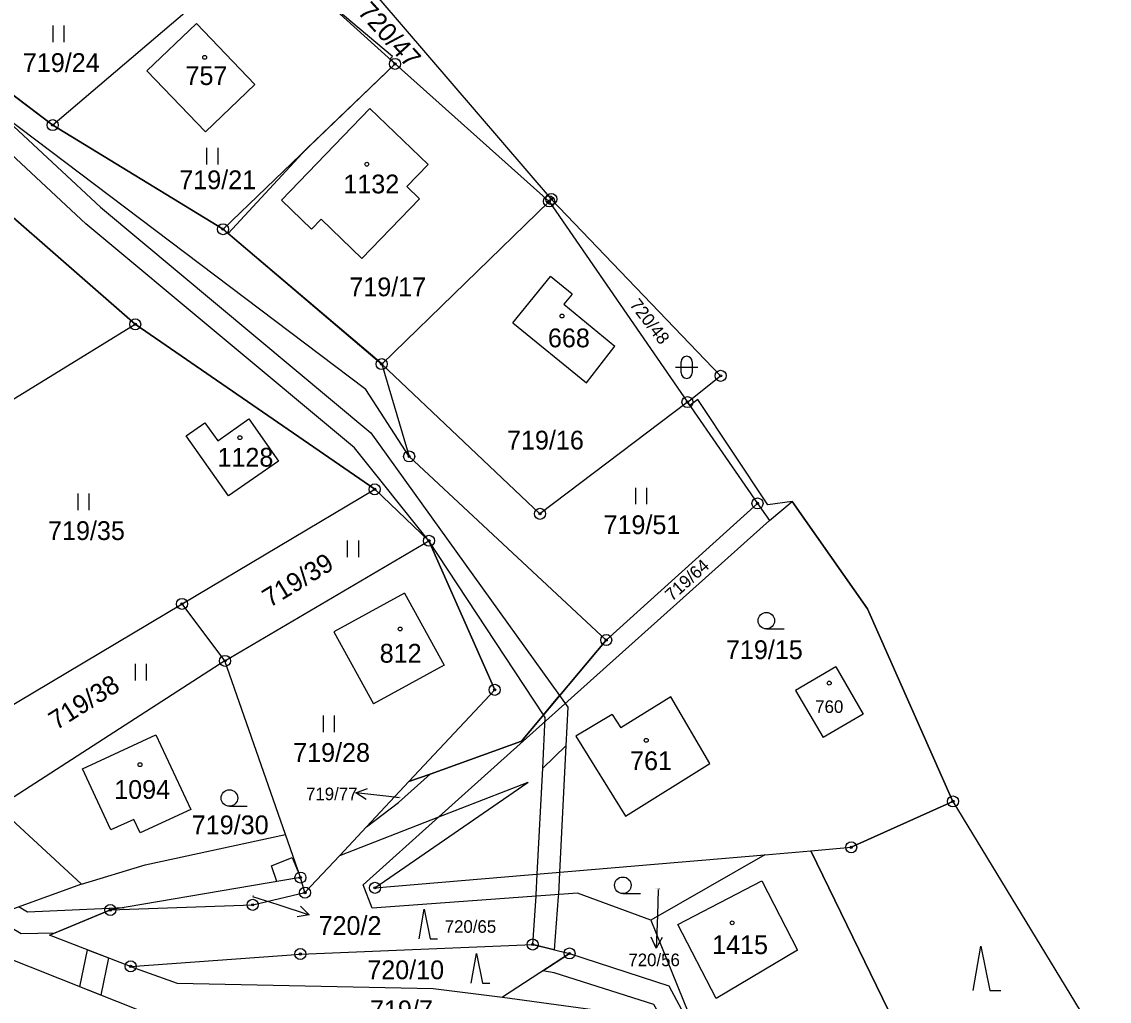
# Model space of a CAD drawing. Extents: x -439246 to -433691, y -1130252 to -1121148.
# Drawn here: x -436567.4 to -436469, y -1125891.5 to -1125802.9 of the extents above; entities that cross this region are included whole.
import ezdxf

# ---------------------------------------------------------------- set-up
doc = ezdxf.new("R2010")
doc.units = 0
for name, color, linetype in [('Vrstva 1', 7, 'Continuous'), ('Vrstva 16', 7, 'Continuous'), ('Vrstva 18', 7, 'Continuous'), ('Vrstva 19', 7, 'Continuous'), ('Vrstva 24', 7, 'Continuous'), ('Vrstva 25', 7, 'Continuous'), ('Vrstva 3', 7, 'Continuous'), ('Vrstva 30', 7, 'Continuous'), ('Vrstva 37', 7, 'Continuous'), ('Vrstva 52', 7, 'Continuous'), ('Vrstva 6', 7, 'Continuous')]:
    doc.layers.add(name, color=color, linetype=linetype)

msp = doc.modelspace()

# ---------------------------------------------------------------- linework, layer by layer
at = {"layer": 'Vrstva 1'}
for p, q in [((-436545.44, -1125795.95), (-436564.59, -1125812.25)), ((-436564.59, -1125812.25), (-436578.24, -1125801.93)), ((-436533.61, -1125806.71), (-436549.17, -1125821.67)), ((-436549.17, -1125821.67), (-436564.59, -1125812.25)), ((-436534.82, -1125833.88), (-436519.67, -1125819.15)), ((-436549.17, -1125821.67), (-436534.82, -1125833.88)), ((-436534.82, -1125833.88), (-436532.33, -1125842.24)), ((-436520.5, -1125847.43), (-436534.82, -1125833.88)), ((-436532.33, -1125842.24), (-436536.26, -1125836.19)), ((-436507.15, -1125837.32), (-436520.5, -1125847.43)), ((-436507.15, -1125837.32), (-436500.81, -1125846.49)), ((-436514.5, -1125858.85), (-436532.33, -1125842.24))]:
    msp.add_line(p, q, dxfattribs=at)
for points in [[(-436541.87, -1125792.85), (-436519.47, -1125818.94)], [(-436536.26, -1125836.19), (-436590.69, -1125795.04)], [(-436545.44, -1125795.95), (-436533.61, -1125806.71)], [(-436594.14, -1125797.88), (-436557.12, -1125830.28)], [(-436551.59, -1125803.04), (-436556.06, -1125807.34)], [(-436551.59, -1125803.04), (-436546.29, -1125808.56)], [(-436519.67, -1125819.15), (-436533.61, -1125806.71)], [(-436556.06, -1125807.34), (-436550.76, -1125812.86)], [(-436546.29, -1125808.56), (-436550.76, -1125812.86)], [(-436543.89, -1125819.04), (-436535.88, -1125810.74)], [(-436535.88, -1125810.74), (-436530.62, -1125815.81)], [(-436530.62, -1125815.81), (-436532.55, -1125817.8)], [(-436532.55, -1125817.8), (-436531.39, -1125818.92)], [(-436541.17, -1125821.67), (-436543.89, -1125819.04)], [(-436531.39, -1125818.92), (-436536.6, -1125824.32)], [(-436519.47, -1125818.94), (-436519.67, -1125819.15)], [(-436507.15, -1125837.32), (-436504.15, -1125834.94), (-436519.47, -1125818.94)], [(-436519.67, -1125819.15), (-436507.15, -1125837.32)], [(-436540.29, -1125820.76), (-436541.17, -1125821.67)], [(-436536.6, -1125824.32), (-436540.29, -1125820.76)], [(-436522.95, -1125830.14), (-436519.53, -1125825.96)], [(-436517.59, -1125827.54), (-436519.53, -1125825.96)], [(-436517.59, -1125827.54), (-436518.35, -1125828.47)], [(-436518.35, -1125828.47), (-436513.71, -1125832.27)], [(-436581.96, -1125845.52), (-436557.12, -1125830.28)], [(-436557.12, -1125830.28), (-436535.45, -1125845.21)], [(-436522.95, -1125830.14), (-436516.29, -1125835.59)], [(-436516.29, -1125835.59), (-436513.71, -1125832.27)], [(-436552.5, -1125840.37), (-436550.81, -1125839.19)], [(-436550.81, -1125839.19), (-436549.66, -1125840.83)], [(-436549.66, -1125840.83), (-436546.83, -1125838.84)], [(-436546.83, -1125838.84), (-436544.15, -1125842.66)], [(-436548.69, -1125845.81), (-436552.5, -1125840.37)], [(-436544.15, -1125842.66), (-436548.69, -1125845.81)], [(-436552.88, -1125855.58), (-436535.45, -1125845.21)], [(-436535.45, -1125845.21), (-436530.54, -1125849.87)], [(-436500.81, -1125846.49), (-436514.5, -1125858.85)], [(-436500.81, -1125846.49), (-436499.73, -1125848.04)], [(-436499.73, -1125848.04), (-436497.68, -1125846.33), (-436490.86, -1125856.02), (-436483.12, -1125873.46)], [(-436529.66, -1125874.86), (-436523.17, -1125869.03), (-436499.73, -1125848.04)], [(-436549, -1125860.74), (-436530.54, -1125849.87)], [(-436530.54, -1125849.87), (-436524.59, -1125863.36)], [(-436532.74, -1125854.6), (-436539.14, -1125858.11)], [(-436532.74, -1125854.6), (-436529.16, -1125861.12)], [(-436570.83, -1125866.25), (-436552.88, -1125855.58)], [(-436549, -1125860.74), (-436552.88, -1125855.58)], [(-436539.14, -1125858.11), (-436535.56, -1125864.63)], [(-436522.18, -1125868.01), (-436514.5, -1125858.85)], [(-436549, -1125860.74), (-436569.55, -1125873.98)], [(-436543.53, -1125876.45), (-436549, -1125860.74)], [(-436529.16, -1125861.12), (-436535.56, -1125864.63)], [(-436493.73, -1125861.29), (-436497.36, -1125863.41)], [(-436493.73, -1125861.29), (-436491.25, -1125865.57)], [(-436524.59, -1125863.36), (-436532.36, -1125871.67)], [(-436508.64, -1125863.99), (-436513.18, -1125866.81)], [(-436505.11, -1125870.04), (-436508.64, -1125863.99)], [(-436497.36, -1125863.41), (-436494.88, -1125867.68)], [(-436513.95, -1125865.58), (-436517.24, -1125867.56)], [(-436513.95, -1125865.58), (-436513.18, -1125866.81)], [(-436491.25, -1125865.57), (-436494.88, -1125867.68)], [(-436561.88, -1125870.5), (-436555.27, -1125867.43)], [(-436555.27, -1125867.43), (-436552.1, -1125874.2)], [(-436530.44, -1125870.98), (-436522.18, -1125868.01)], [(-436517.24, -1125867.56), (-436512.76, -1125874.78)], [(-436512.76, -1125874.78), (-436505.11, -1125870.04)], [(-436559.33, -1125876.03), (-436561.88, -1125870.5)], [(-436536.2, -1125875.77), (-436533.3, -1125873.55), (-436530.44, -1125870.98)], [(-436532.36, -1125871.67), (-436530.44, -1125870.98)], [(-436532.36, -1125871.67), (-436536.2, -1125875.77)], [(-436535.43, -1125881.28), (-436521.57, -1125871.71)], [(-436529.66, -1125874.86), (-436521.57, -1125871.71)], [(-436569.55, -1125873.98), (-436561.98, -1125880.95)], [(-436552.1, -1125874.2), (-436556.66, -1125876.31)], [(-436483.12, -1125873.46), (-436492.33, -1125877.61)], [(-436557.26, -1125875.09), (-436559.33, -1125876.03)], [(-436556.66, -1125876.31), (-436557.26, -1125875.09)], [(-436538.6, -1125878.34), (-436529.66, -1125874.86)], [(-436536.5, -1125881), (-436529.66, -1125874.86)], [(-436536.2, -1125875.77), (-436538.6, -1125878.34)], [(-436556.21, -1125879.19), (-436543.53, -1125876.45)], [(-436542.17, -1125880.35), (-436543.53, -1125876.45)], [(-436500.14, -1125878.28), (-436495.97, -1125877.92)], [(-436495.97, -1125877.92), (-436492.33, -1125877.61)], [(-436495.97, -1125877.92), (-436475.95, -1125919.12), (-436482.11, -1125922.67)], [(-436538.6, -1125878.34), (-436541.76, -1125881.71)], [(-436535.43, -1125881.28), (-436500.14, -1125878.28)], [(-436500.14, -1125878.28), (-436510.45, -1125884.2)], [(-436561.98, -1125880.95), (-436556.21, -1125879.19)], [(-436561.98, -1125880.95), (-436568.15, -1125883.19)], [(-436542.17, -1125880.35), (-436559.37, -1125883.28)], [(-436541.76, -1125881.71), (-436542.17, -1125880.35)], [(-436535.69, -1125883.12), (-436536.5, -1125881)], [(-436508.01, -1125884.59), (-436500.43, -1125880.64), (-436497.2, -1125886.91), (-436504.55, -1125891.31), (-436508.01, -1125884.59)], [(-436546.49, -1125882.82), (-436541.76, -1125881.71)], [(-436517.1, -1125881.75), (-436535.69, -1125883.12)], [(-436510.45, -1125884.2), (-436517.1, -1125881.75)], [(-436559.37, -1125883.28), (-436546.49, -1125882.82)], [(-436564.87, -1125885.56), (-436559.37, -1125883.28)], [(-436510.45, -1125884.2), (-436505.63, -1125896.13)], [(-436557.54, -1125888.39), (-436564.87, -1125885.56)], [(-436571.96, -1125886.32), (-436553.5, -1125893.66)], [(-436542.18, -1125887.27), (-436521.15, -1125886.41)], [(-436521.15, -1125886.41), (-436517.82, -1125887.22)], [(-436557.54, -1125888.39), (-436542.18, -1125887.27)], [(-436517.82, -1125887.22), (-436523.9, -1125891.18)], [(-436557.54, -1125888.39), (-436553.33, -1125889.91)], [(-436553.33, -1125889.91), (-436530.15, -1125890.38)], [(-436530.15, -1125890.38), (-436523.9, -1125891.18)], [(-436523.9, -1125891.18), (-436510.19, -1125893.05)]]:
    msp.add_lwpolyline(points, dxfattribs=at)
at = {"layer": 'Vrstva 16'}
for p, q in [((-436534.17, -1125873.02), (-436537.152, -1125872.69)), ((-436544.22, -1125882.8), (-436541.37, -1125883.736)), ((-436509.87, -1125883.75), (-436509.971, -1125886.748))]:
    msp.add_line(p, q, dxfattribs=at)
for points in [[(-436536.213, -1125873.297), (-436537.152, -1125872.69), (-436536.103, -1125872.303)], [(-436533.24, -1125873.12), (-436534.17, -1125873.02)], [(-436546.5, -1125882.05), (-436544.22, -1125882.8)], [(-436509.8, -1125881.43), (-436509.87, -1125883.75)], [(-436542.164, -1125882.949), (-436541.37, -1125883.736), (-436542.476, -1125883.899)], [(-436509.438, -1125885.766), (-436509.971, -1125886.748), (-436510.437, -1125885.732)]]:
    msp.add_lwpolyline(points, dxfattribs=at)
at = {"layer": 'Vrstva 24'}
for centre, radius in [((-436533.61, -1125806.71), 0.5), ((-436533.61, -1125806.71), 0.1), ((-436564.59, -1125812.25), 0.5), ((-436564.59, -1125812.25), 0.1), ((-436519.67, -1125819.15), 0.5), ((-436519.47, -1125818.94), 0.5), ((-436519.67, -1125819.15), 0.1), ((-436519.47, -1125818.94), 0.1), ((-436549.17, -1125821.67), 0.5), ((-436549.17, -1125821.67), 0.1), ((-436557.12, -1125830.28), 0.5), ((-436557.12, -1125830.28), 0.1), ((-436534.82, -1125833.88), 0.5), ((-436534.82, -1125833.88), 0.1), ((-436504.15, -1125834.94), 0.5), ((-436504.15, -1125834.94), 0.1), ((-436507.15, -1125837.32), 0.5), ((-436507.15, -1125837.32), 0.1), ((-436532.33, -1125842.24), 0.5), ((-436532.33, -1125842.24), 0.1), ((-436535.45, -1125845.21), 0.5), ((-436535.45, -1125845.21), 0.1), ((-436500.81, -1125846.49), 0.5), ((-436500.81, -1125846.49), 0.1), ((-436520.5, -1125847.43), 0.5), ((-436520.5, -1125847.43), 0.1), ((-436530.54, -1125849.87), 0.5), ((-436530.54, -1125849.87), 0.1), ((-436552.88, -1125855.58), 0.5), ((-436552.88, -1125855.58), 0.1), ((-436514.5, -1125858.85), 0.5), ((-436514.5, -1125858.85), 0.1), ((-436549, -1125860.74), 0.5), ((-436549, -1125860.74), 0.1), ((-436524.59, -1125863.36), 0.5), ((-436524.59, -1125863.36), 0.1), ((-436483.12, -1125873.46), 0.5), ((-436483.12, -1125873.46), 0.1), ((-436492.33, -1125877.61), 0.5), ((-436492.33, -1125877.61), 0.1), ((-436542.17, -1125880.35), 0.5), ((-436542.17, -1125880.35), 0.1), ((-436535.43, -1125881.28), 0.5), ((-436541.76, -1125881.71), 0.5), ((-436541.76, -1125881.71), 0.1), ((-436535.43, -1125881.28), 0.1), ((-436559.37, -1125883.28), 0.5), ((-436546.49, -1125882.82), 0.5), ((-436546.49, -1125882.82), 0.1), ((-436559.37, -1125883.28), 0.1), ((-436521.15, -1125886.41), 0.5), ((-436542.18, -1125887.27), 0.5), ((-436521.15, -1125886.41), 0.1), ((-436517.82, -1125887.22), 0.5), ((-436557.54, -1125888.39), 0.5), ((-436542.18, -1125887.27), 0.1), ((-436517.82, -1125887.22), 0.1), ((-436557.54, -1125888.39), 0.1)]:
    msp.add_circle(centre, radius, dxfattribs=at)
at = {"layer": 'Vrstva 25'}
for p, q in [((-436564.54, -1125804.74), (-436564.54, -1125803.24)), ((-436563.54, -1125804.74), (-436563.54, -1125803.24)), ((-436550.63, -1125815.81), (-436550.63, -1125814.31)), ((-436549.63, -1125815.81), (-436549.63, -1125814.31)), ((-436507.72, -1125834.67), (-436507.72, -1125833.67)), ((-436506.72, -1125833.67), (-436506.72, -1125834.67)), ((-436508.22, -1125834.17), (-436506.22, -1125834.17)), ((-436562.28, -1125847.1), (-436562.28, -1125845.6)), ((-436561.28, -1125847.1), (-436561.28, -1125845.6)), ((-436511.83, -1125846.57), (-436511.83, -1125845.07)), ((-436510.83, -1125846.57), (-436510.83, -1125845.07)), ((-436537.9, -1125851.34), (-436537.9, -1125849.84)), ((-436536.9, -1125851.34), (-436536.9, -1125849.84)), ((-436500.01, -1125857.85), (-436498.41, -1125857.85)), ((-436557.1, -1125862.52), (-436557.1, -1125861.02)), ((-436556.1, -1125862.52), (-436556.1, -1125861.02)), ((-436540.08, -1125867.18), (-436540.08, -1125865.68)), ((-436539.08, -1125867.18), (-436539.08, -1125865.68)), ((-436548.6, -1125873.9), (-436547, -1125873.9)), ((-436513, -1125881.8), (-436511.4, -1125881.8))]:
    msp.add_line(p, q, dxfattribs=at)
for points in [[(-436531.439, -1125885.9), (-436530.97, -1125883.22), (-436530.434, -1125885.9), (-436529.764, -1125885.9)], [(-436481.29, -1125890.57), (-436480.59, -1125886.57), (-436479.79, -1125890.57), (-436478.79, -1125890.57)], [(-436526.709, -1125889.91), (-436526.24, -1125887.23), (-436525.704, -1125889.91), (-436525.034, -1125889.91)]]:
    msp.add_lwpolyline(points, dxfattribs=at)
for centre, radius in [((-436550.84, -1125806.12), 0.175), ((-436536.16, -1125815.79), 0.175), ((-436518.5, -1125829.53), 0.175), ((-436547.65, -1125840.54), 0.175), ((-436500.01, -1125857.1), 0.75), ((-436533.15, -1125857.85), 0.175), ((-436494.32, -1125862.75), 0.175), ((-436510.88, -1125867.93), 0.175), ((-436556.69, -1125870.13), 0.175), ((-436548.6, -1125873.15), 0.75), ((-436513, -1125881.05), 0.75), ((-436503.1, -1125884.45), 0.175)]:
    msp.add_circle(centre, radius, dxfattribs=at)
for centre, start, end in [((-436507.22, -1125833.67), 0, 180), ((-436507.22, -1125834.67), 180, 0)]:
    msp.add_arc(centre, 0.5, start, end, dxfattribs=at)
at = {"layer": 'Vrstva 3'}
for points in [[(-436551.59, -1125803.04), (-436556.06, -1125807.34)], [(-436551.59, -1125803.04), (-436546.29, -1125808.56)], [(-436556.06, -1125807.34), (-436550.76, -1125812.86)], [(-436546.29, -1125808.56), (-436550.76, -1125812.86)], [(-436543.89, -1125819.04), (-436535.88, -1125810.74)], [(-436535.88, -1125810.74), (-436530.62, -1125815.81)], [(-436530.62, -1125815.81), (-436532.55, -1125817.8)], [(-436532.55, -1125817.8), (-436531.39, -1125818.92)], [(-436541.17, -1125821.67), (-436543.89, -1125819.04)], [(-436531.39, -1125818.92), (-436536.6, -1125824.32)], [(-436540.29, -1125820.76), (-436541.17, -1125821.67)], [(-436536.6, -1125824.32), (-436540.29, -1125820.76)], [(-436522.95, -1125830.14), (-436519.53, -1125825.96)], [(-436517.59, -1125827.54), (-436519.53, -1125825.96)], [(-436517.59, -1125827.54), (-436518.35, -1125828.47)], [(-436518.35, -1125828.47), (-436513.71, -1125832.27)], [(-436522.95, -1125830.14), (-436516.29, -1125835.59)], [(-436516.29, -1125835.59), (-436513.71, -1125832.27)], [(-436552.5, -1125840.37), (-436550.81, -1125839.19)], [(-436550.81, -1125839.19), (-436549.66, -1125840.83)], [(-436549.66, -1125840.83), (-436546.83, -1125838.84)], [(-436546.83, -1125838.84), (-436544.15, -1125842.66)], [(-436548.69, -1125845.81), (-436552.5, -1125840.37)], [(-436544.15, -1125842.66), (-436548.69, -1125845.81)], [(-436532.74, -1125854.6), (-436539.14, -1125858.11)], [(-436532.74, -1125854.6), (-436529.16, -1125861.12)], [(-436539.14, -1125858.11), (-436535.56, -1125864.63)], [(-436529.16, -1125861.12), (-436535.56, -1125864.63)], [(-436493.73, -1125861.29), (-436497.36, -1125863.41)], [(-436493.73, -1125861.29), (-436491.25, -1125865.57)], [(-436508.64, -1125863.99), (-436513.18, -1125866.81)], [(-436505.11, -1125870.04), (-436508.64, -1125863.99)], [(-436497.36, -1125863.41), (-436494.88, -1125867.68)], [(-436513.95, -1125865.58), (-436517.24, -1125867.56)], [(-436513.95, -1125865.58), (-436513.18, -1125866.81)], [(-436491.25, -1125865.57), (-436494.88, -1125867.68)], [(-436561.88, -1125870.5), (-436555.27, -1125867.43)], [(-436555.27, -1125867.43), (-436552.1, -1125874.2)], [(-436517.24, -1125867.56), (-436512.76, -1125874.78)], [(-436512.76, -1125874.78), (-436505.11, -1125870.04)], [(-436559.33, -1125876.03), (-436561.88, -1125870.5)], [(-436552.1, -1125874.2), (-436556.66, -1125876.31)], [(-436557.26, -1125875.09), (-436559.33, -1125876.03)], [(-436556.66, -1125876.31), (-436557.26, -1125875.09)], [(-436508.01, -1125884.59), (-436500.43, -1125880.64), (-436497.2, -1125886.91), (-436504.55, -1125891.31), (-436508.01, -1125884.59)]]:
    msp.add_lwpolyline(points, dxfattribs=at)
at = {"layer": 'Vrstva 30'}
for points in [[(-436618.91, -1125747.99), (-436609.65, -1125760.8), (-436597.82, -1125777.17), (-436589.43, -1125791.49), (-436578.24, -1125801.93), (-436564.59, -1125812.25), (-436549.17, -1125821.67), (-436534.82, -1125833.88), (-436532.33, -1125842.24), (-436514.5, -1125858.85)], [(-436557.12, -1125830.28), (-436594.14, -1125797.88), (-436602.6, -1125783.85), (-436601.17, -1125782.81), (-436626.22, -1125753.57)], [(-436537.28, -1125841.47), (-436561.59, -1125821.17), (-436576.5, -1125807.32), (-436584.92, -1125799.4), (-436592.05, -1125792.7), (-436590, -1125790.52), (-436589.43, -1125791.49), (-436578.24, -1125801.93), (-436575.13, -1125805.86), (-436560.26, -1125819.67), (-436535.8, -1125840.1), (-436518.72, -1125863.88), (-436520.18, -1125865.63), (-436530.54, -1125849.87), (-436537.28, -1125841.47)], [(-436535.45, -1125845.21), (-436557.12, -1125830.28)], [(-436514.5, -1125858.85), (-436522.18, -1125868.01), (-436530.44, -1125870.98), (-436532.36, -1125871.67), (-436524.59, -1125863.36), (-436530.54, -1125849.87), (-436535.45, -1125845.21)], [(-436520.02, -1125865.86), (-436520.18, -1125865.63), (-436518.72, -1125863.88)], [(-436518.72, -1125863.88), (-436517.97, -1125864.93)], [(-436517.97, -1125864.93), (-436518.15, -1125868.43), (-436520.25, -1125870.44), (-436520.02, -1125865.86)], [(-436520.74, -1125880.03), (-436520.25, -1125870.44), (-436518.15, -1125868.43), (-436518.73, -1125879.86), (-436518.83, -1125881.88), (-436518.84, -1125882.07), (-436519.21, -1125886.88), (-436521.15, -1125886.41), (-436520.84, -1125882.03), (-436520.83, -1125881.9), (-436520.74, -1125880.03)], [(-436544.3, -1125880.71), (-436544.78, -1125879.28), (-436542.93, -1125878.52), (-436542.17, -1125880.35), (-436544.3, -1125880.71)], [(-436567.63, -1125883), (-436566.88, -1125883.44)], [(-436566.88, -1125883.44), (-436558.11, -1125883.07), (-436559.37, -1125883.28), (-436564.43, -1125885.38)], [(-436564.43, -1125885.38), (-436567.44, -1125885.43), (-436570.36, -1125883.73)], [(-436562.13, -1125890.23), (-436561.43, -1125886.89), (-436559.54, -1125887.62), (-436560.24, -1125890.98), (-436562.13, -1125890.23)], [(-436510.18, -1125891.83), (-436519.21, -1125888.98), (-436520.24, -1125888.8), (-436517.82, -1125887.22), (-436508.82, -1125890.16), (-436505.63, -1125896.13), (-436509.09, -1125893.79), (-436510.18, -1125891.83)]]:
    msp.add_lwpolyline(points, dxfattribs=at)
at = {"layer": 'Vrstva 37'}
for centre in [(-436550.84, -1125806.12), (-436536.16, -1125815.79), (-436518.5, -1125829.53), (-436547.65, -1125840.54), (-436533.15, -1125857.85), (-436494.32, -1125862.75), (-436510.88, -1125867.93), (-436556.69, -1125870.13), (-436503.1, -1125884.45)]:
    msp.add_circle(centre, 0.175, dxfattribs=at)
at = {"layer": 'Vrstva 52'}
msp.add_lwpolyline([(-436471.75, -1125940.16), (-436475.94, -1125932.43), (-436475.95, -1125919.12), (-436495.97, -1125877.92), (-436492.33, -1125877.61), (-436483.12, -1125873.46), (-436490.86, -1125856.02), (-436497.68, -1125846.33), (-436499.89, -1125846.62), (-436506.2, -1125837.08), (-436506.94, -1125837.62), (-436507.15, -1125837.32), (-436520.5, -1125847.43), (-436534.8, -1125833.88), (-436534.85, -1125833.83), (-436548.72, -1125822.05), (-436541.62, -1125814.41), (-436533.61, -1125806.71), (-436534.07, -1125806.29), (-436533.84, -1125806.04), (-436541.19, -1125799.82)], dxfattribs=at)
at = {"layer": 'Vrstva 6'}
msp.add_lwpolyline([(-436483.12, -1125873.46), (-436468.98, -1125896.74)], dxfattribs=at)

# ---------------------------------------------------------------- texts
at = {"layer": 'Vrstva 16'}
for s, height, p in [('719/77', 1.14, (-436541.667, -1125873.35)), ('720/2', 1.7, (-436540.53, -1125885.54)), ('720/56', 1.14, (-436512.497, -1125888.37))]:
    msp.add_text(s, height=height, dxfattribs=at).set_placement(p)
at = {"layer": 'Vrstva 18'}
for s, height, rotation, p in [('720/47', 1.7, 312.17427, (-436537.062, -1125802.064)), ('720/48', 1.14, 307.79667, (-436512.441, -1125828.522)), ('719/39', 1.7, 31.21785, (-436544.955, -1125855.953)), ('719/64', 1.14, 41.9751, (-436508.54, -1125855.398)), ('719/38', 1.7, 32.25762, (-436564.255, -1125867.046))]:
    msp.add_text(s, height=height, rotation=rotation, dxfattribs=at).set_placement(p)
for s, height, p in [('719/24', 1.7, (-436567.289, -1125807.44)), ('719/21', 1.7, (-436553.136, -1125818.05)), ('719/17', 1.7, (-436537.746, -1125827.74)), ('719/16', 1.7, (-436523.478, -1125841.61)), ('719/51', 1.7, (-436514.746, -1125849.27)), ('719/35', 1.7, (-436565.009, -1125849.8)), ('719/15', 1.7, (-436503.666, -1125860.58)), ('719/28', 1.7, (-436542.829, -1125869.88)), ('719/77', 0.1, (-436533.451, -1125873.12)), ('719/30', 1.7, (-436552.004, -1125876.43)), ('720/2', 0.1, (-436546.701, -1125882.05)), ('720/56', 0.1, (-436510.033, -1125881.43)), ('720/65', 1.14, (-436529.117, -1125885.35)), ('720/10', 1.7, (-436536.123, -1125889.55)), ('719/7', 1.7, (-436535.876, -1125893.17))]:
    msp.add_text(s, height=height, dxfattribs=at).set_placement(p)
at = {"layer": 'Vrstva 19'}
for s, height, p in [('757', 1.7, (-436552.572, -1125808.62)), ('1132', 1.7, (-436538.289, -1125818.43)), ('668', 1.7, (-436519.774, -1125832.36)), ('1128', 1.7, (-436549.679, -1125843.16)), ('812', 1.7, (-436534.999, -1125860.9)), ('760', 1.14, (-436495.589, -1125865.45)), ('761', 1.7, (-436512.34, -1125870.63)), ('1094', 1.7, (-436559.023, -1125873.23)), ('1415', 1.7, (-436504.919, -1125887.28))]:
    msp.add_text(s, height=height, dxfattribs=at).set_placement(p)

doc.saveas('drawing.dxf')
